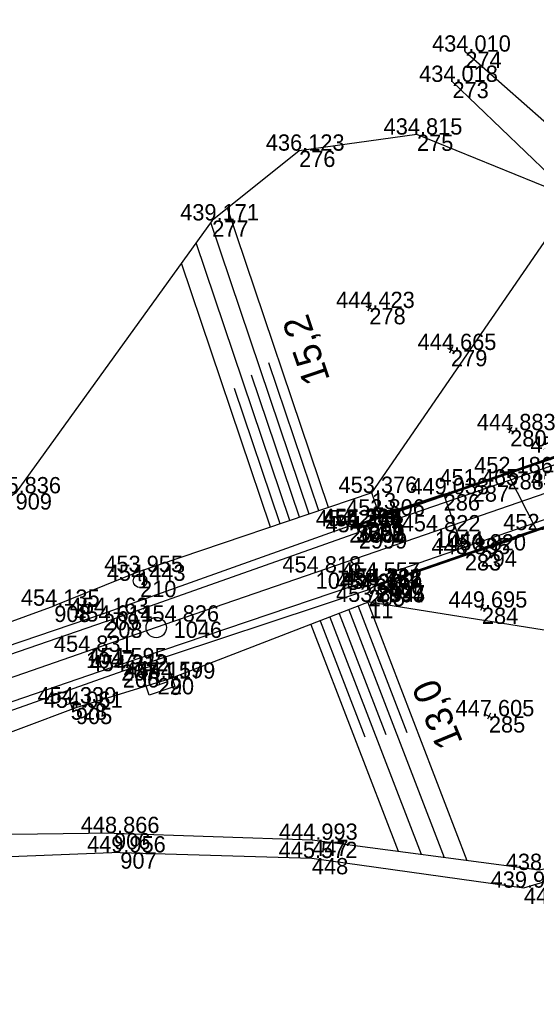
# Model space of a CAD drawing. Extents: x -751615 to -750797, y -1114905 to -1114561.
# Drawn here: x -751212.2 to -751174.1, y -1114734.9 to -1114663.2 of the extents above; entities that cross this region are included whole.
import ezdxf

# ---------------------------------------------------------------- set-up
doc = ezdxf.new("R2010")
doc.units = 0
for name, color, linetype in [('Vrstva 1', 7, 'Continuous'), ('Vrstva 17', 7, 'Continuous'), ('Vrstva 18', 7, 'Continuous'), ('Vrstva 33', 7, 'Continuous'), ('Vrstva 4', 7, 'Continuous'), ('Vrstva 48', 7, 'Continuous'), ('Vrstva 49', 7, 'Continuous'), ('Vrstva 51', 7, 'Continuous'), ('Vrstva 60', 7, 'Continuous'), ('Vrstva 61', 7, 'Continuous'), ('Vrstva 7', 7, 'Continuous')]:
    doc.layers.add(name, color=color, linetype=linetype)

msp = doc.modelspace()

# ---------------------------------------------------------------- linework, layer by layer
at = {"layer": 'Vrstva 1'}
msp.add_lwpolyline([(-751049.798, -1114655.49), (-751059.246, -1114658.755), (-751068.733, -1114662.026), (-751078.259, -1114665.311), (-751087.386, -1114668.46), (-751094.716, -1114670.988), (-751098.18, -1114672.185), (-751107.899, -1114675.542), (-751117.566, -1114678.875), (-751127.151, -1114682.181), (-751136.66, -1114685.456), (-751145.831, -1114688.627), (-751153.169, -1114691.158), (-751162.606, -1114694.412), (-751172.056, -1114697.672), (-751181.572, -1114700.954), (-751190.356, -1114703.987), (-751200.827, -1114707.603), (-751207.289, -1114709.832), (-751216.509, -1114713.014)], dxfattribs=at)
at = {"layer": 'Vrstva 17'}
for points in [[(-751142.673, -1114685.146), (-751163.635, -1114692.354), (-751187.36, -1114700.537)], [(-751141.251, -1114689.537), (-751162.016, -1114696.742), (-751185.869, -1114704.919)]]:
    msp.add_lwpolyline(points, dxfattribs=at)
at = {"layer": 'Vrstva 18'}
for p, q in [((-751176.227, -1114696.67), (-751174.085, -1114700.864)), ((-751180.926, -1114698.222), (-751185.664, -1114699.79)), ((-751179.366, -1114702.637), (-751180.926, -1114698.222)), ((-751185.664, -1114699.79), (-751187.351, -1114700.583)), ((-751179.366, -1114702.637), (-751185.916, -1114704.887))]:
    msp.add_line(p, q, dxfattribs=at)
for points in [[(-751047.485, -1114652.852), (-751074.245, -1114662.097), (-751099.037, -1114670.633), (-751120.593, -1114678.106), (-751141.938, -1114685.464), (-751163.608, -1114692.915), (-751187.181, -1114701.023)], [(-751046.217, -1114656.195), (-751073.081, -1114665.441), (-751097.909, -1114674.024), (-751119.627, -1114681.519), (-751140.891, -1114688.815), (-751162.437, -1114696.278), (-751186.019, -1114704.426)], [(-751142.792, -1114685.118), (-751163.784, -1114692.357), (-751187.386, -1114700.477)], [(-751142.793, -1114685.119), (-751163.784, -1114692.356), (-751187.386, -1114700.477)], [(-751142.776, -1114685.241), (-751163.709, -1114692.446), (-751187.351, -1114700.583)], [(-751141.364, -1114689.506), (-751162.365, -1114696.76), (-751185.916, -1114704.887)], [(-751141.333, -1114689.609), (-751162.305, -1114696.864), (-751185.867, -1114704.985)], [(-751141.334, -1114689.6), (-751162.302, -1114696.872), (-751185.866, -1114704.984)], [(-751187.181, -1114701.023), (-751187.386, -1114700.477), (-751187.386, -1114700.477), (-751187.351, -1114700.583), (-751187.181, -1114701.023)], [(-751186.019, -1114704.426), (-751185.867, -1114704.985), (-751185.866, -1114704.984), (-751185.916, -1114704.887), (-751186.019, -1114704.426)]]:
    msp.add_lwpolyline(points, dxfattribs=at)
for centre, major_axis, ratio, start_param, end_param in [((-751176.059, -1114696.183), (5.5, 1.848), 0.070466, 4.658245, 6.265164), ((-751176.321, -1114696.416), (5.121, 1.873), 0.049725, 3.576163, 4.712471), ((-751175.104, -1114700.819), (4.529, 1.783), 0.086973, 3.454221, 4.905011)]:
    msp.add_ellipse(centre, major_axis=major_axis, ratio=ratio, start_param=start_param, end_param=end_param, dxfattribs=at)
at = {"layer": 'Vrstva 33'}
for p, q in [((-751201.835, -1114712.237), (-751202.161, -1114711.291)), ((-751201.362, -1114712.074), (-751202.308, -1114712.4))]:
    msp.add_line(p, q, dxfattribs=at)
msp.add_lwpolyline([(-751200.727, -1114712.383), (-751202.617, -1114713.035), (-751203.269, -1114711.145), (-751201.379, -1114710.493), (-751200.727, -1114712.383)], dxfattribs=at)
at = {"layer": 'Vrstva 4'}
for p, q in [((-751205.795, -1114707.603), (-751187.181, -1114701.023)), ((-751204.677, -1114710.75), (-751186.019, -1114704.426))]:
    msp.add_line(p, q, dxfattribs=at)
for points in [[(-751047.485, -1114652.852), (-751074.245, -1114662.097), (-751099.037, -1114670.633), (-751120.593, -1114678.106), (-751141.938, -1114685.464), (-751163.608, -1114692.915), (-751187.181, -1114701.023)], [(-751046.217, -1114656.195), (-751073.081, -1114665.441), (-751097.909, -1114674.024), (-751119.627, -1114681.519), (-751140.891, -1114688.815), (-751162.437, -1114696.278), (-751186.019, -1114704.426)], [(-751187.894, -1114700.58), (-751206.028, -1114707.041), (-751231.235, -1114715.596), (-751249.544, -1114721.971), (-751267.723, -1114728.471), (-751285.298, -1114734.541), (-751305.686, -1114741.509), (-751323.628, -1114747.668), (-751344.164, -1114754.785), (-751362.443, -1114761.123), (-751382.646, -1114767.996), (-751419.827, -1114780.907), (-751439.841, -1114787.752), (-751459.648, -1114794.565), (-751479.262, -1114801.395), (-751499.563, -1114808.301), (-751517.656, -1114814.613), (-751524.467, -1114817.135), (-751524.911, -1114817.646)], [(-751187.894, -1114700.58), (-751187.351, -1114700.583), (-751187.181, -1114701.023)], [(-751186.455, -1114705.269), (-751185.916, -1114704.887), (-751186.019, -1114704.426)], [(-751186.455, -1114705.269), (-751204.57, -1114711.262), (-751229.26, -1114719.967), (-751248.511, -1114726.389), (-751266.031, -1114732.591), (-751283.828, -1114738.73), (-751304.211, -1114745.766), (-751322.374, -1114751.898), (-751342.612, -1114758.897), (-751360.965, -1114765.168), (-751381.114, -1114772.121), (-751418.537, -1114784.997), (-751438.613, -1114791.912), (-751458.172, -1114798.656), (-751477.814, -1114805.419), (-751497.901, -1114812.476), (-751516.513, -1114818.688), (-751522.385, -1114820.606), (-751523.195, -1114820.521)], [(-751205.795, -1114707.603), (-751230.97, -1114716.264), (-751249.417, -1114722.675), (-751267.451, -1114728.869), (-751285.106, -1114734.872), (-751305.56, -1114741.936), (-751323.346, -1114748.135), (-751343.956, -1114755.234), (-751362.406, -1114761.583), (-751382.455, -1114768.543), (-751419.68, -1114781.407), (-751439.787, -1114788.305), (-751459.372, -1114795.057), (-751479.147, -1114801.881), (-751499.337, -1114808.873), (-751517.572, -1114815.159), (-751524.911, -1114817.646)], [(-751204.677, -1114710.75), (-751229.564, -1114719.281), (-751248.527, -1114725.936), (-751266.247, -1114732.037), (-751284.071, -1114738.15), (-751304.213, -1114745.084), (-751322.473, -1114751.338), (-751342.638, -1114758.269), (-751361.135, -1114764.639), (-751381.339, -1114771.707), (-751418.714, -1114784.623), (-751438.728, -1114791.466), (-751458.255, -1114798.22), (-751477.955, -1114804.997), (-751498.184, -1114811.907), (-751516.629, -1114818.238), (-751523.195, -1114820.521)]]:
    msp.add_lwpolyline(points, dxfattribs=at)
at = {"layer": 'Vrstva 48'}
for p, q in [((-751189.418, -1114699.201), (-751196.867, -1114677.15)), ((-751190.839, -1114699.681), (-751198.095, -1114678.2)), ((-751192.26, -1114700.161), (-751199.173, -1114679.696)), ((-751193.682, -1114700.641), (-751200.251, -1114681.192)), ((-751190.129, -1114699.441), (-751193.809, -1114688.545)), ((-751191.55, -1114699.921), (-751195.092, -1114689.435)), ((-751192.971, -1114700.401), (-751196.342, -1114690.423)), ((-751187.924, -1114706.736), (-751180.903, -1114724.972)), ((-751187.224, -1114706.466), (-751183.64, -1114715.775)), ((-751186.524, -1114706.197), (-751179.209, -1114725.197)), ((-751190.023, -1114707.544), (-751186.734, -1114716.089)), ((-751189.324, -1114707.275), (-751182.597, -1114724.747)), ((-751188.624, -1114707.005), (-751185.187, -1114715.932)), ((-751190.723, -1114707.814), (-751184.291, -1114724.521))]:
    msp.add_line(p, q, dxfattribs=at)
at = {"layer": 'Vrstva 49'}
for p, q in [((-751186.22, -1114698.121), (-751171.305, -1114676.437)), ((-751186.182, -1114684.61), (-751186.632, -1114684.39)), ((-751186.297, -1114684.275), (-751186.517, -1114684.725)), ((-751180.163, -1114687.702), (-751180.613, -1114687.482)), ((-751180.278, -1114687.367), (-751180.498, -1114687.817)), ((-751175.803, -1114693.61), (-751176.253, -1114693.39)), ((-751175.918, -1114693.275), (-751176.138, -1114693.725)), ((-751203.477, -1114703.95), (-751209.62, -1114706.435)), ((-751186.41, -1114706.153), (-751159.892, -1114710.39)), ((-751231.525, -1114714.481), (-751209.62, -1114706.435)), ((-751177.885, -1114706.682), (-751178.335, -1114706.462)), ((-751178, -1114706.347), (-751178.22, -1114706.797)), ((-751177.37, -1114714.687), (-751177.82, -1114714.467)), ((-751177.485, -1114714.352), (-751177.705, -1114714.802))]:
    msp.add_line(p, q, dxfattribs=at)
for points in [[(-751159.892, -1114710.39), (-751159.564, -1114697.887), (-751162.611, -1114687.691), (-751171.305, -1114676.437), (-751182.896, -1114671.724), (-751191.58, -1114672.907), (-751197.985, -1114678.047), (-751212.472, -1114698.152), (-751234.949, -1114713.279), (-751244.9, -1114718.575)], [(-751185.664, -1114699.79), (-751186.22, -1114698.121), (-751203.477, -1114703.95)], [(-751185.916, -1114704.887), (-751179.366, -1114702.637), (-751180.926, -1114698.222), (-751185.664, -1114699.79)], [(-751185.916, -1114704.887), (-751186.41, -1114706.153), (-751201.101, -1114711.809)], [(-751201.101, -1114711.809), (-751208.027, -1114713.956), (-751228.322, -1114721.57), (-751240.07, -1114724.297)], [(-751205.217, -1114723.182), (-751227.836, -1114723.486), (-751240.236, -1114725.654)], [(-751205.217, -1114723.182), (-751190.613, -1114723.681), (-751173.898, -1114725.903), (-751163.172, -1114723.646)], [(-751204.754, -1114724.609), (-751190.638, -1114725.023), (-751175.014, -1114727.21), (-751163.172, -1114723.646)], [(-751204.754, -1114724.609), (-751227.195, -1114725.505), (-751238.195, -1114726.494), (-751253.205, -1114735.378), (-751297.853, -1114756.709), (-751332.903, -1114772.385), (-751375.498, -1114786.511), (-751400.696, -1114793.558), (-751443.206, -1114803.356), (-751482.539, -1114812.284)]]:
    msp.add_lwpolyline(points, dxfattribs=at)
at = {"layer": 'Vrstva 51'}
for points in [[(-751179.332, -1114665.61), (-751169.189, -1114674.547), (-751160.093, -1114686.607), (-751155.976, -1114695.63), (-751150.02, -1114707.804), (-751142.251, -1114727.926)], [(-751180.281, -1114667.838), (-751171.305, -1114676.437), (-751162.611, -1114687.691), (-751158.117, -1114696.777), (-751151.768, -1114708.954), (-751144.608, -1114729.118)]]:
    msp.add_lwpolyline(points, dxfattribs=at)
at = {"layer": 'Vrstva 60'}
for p, q in [((-751179.332, -1114665.61), (-751179.332, -1114665.61)), ((-751180.281, -1114667.838), (-751180.281, -1114667.838)), ((-751182.896, -1114671.724), (-751182.896, -1114671.724)), ((-751191.58, -1114672.907), (-751191.58, -1114672.907)), ((-751197.985, -1114678.047), (-751197.985, -1114678.047)), ((-751186.407, -1114684.5), (-751186.407, -1114684.5)), ((-751180.388, -1114687.592), (-751180.388, -1114687.592)), ((-751176.028, -1114693.5), (-751176.028, -1114693.5)), ((-751176.227, -1114696.67), (-751176.227, -1114696.67)), ((-751186.22, -1114698.121), (-751186.22, -1114698.121)), ((-751180.926, -1114698.222), (-751180.926, -1114698.222)), ((-751178.786, -1114697.568), (-751178.786, -1114697.568)), ((-751185.664, -1114699.79), (-751185.664, -1114699.79)), ((-751187.894, -1114700.58), (-751187.894, -1114700.58)), ((-751187.386, -1114700.477), (-751187.386, -1114700.477)), ((-751187.386, -1114700.477), (-751187.386, -1114700.477)), ((-751187.36, -1114700.537), (-751187.36, -1114700.537)), ((-751187.351, -1114700.583), (-751187.351, -1114700.583)), ((-751187.181, -1114701.023), (-751187.181, -1114701.023)), ((-751181.572, -1114700.954), (-751181.572, -1114700.954)), ((-751174.085, -1114700.864), (-751174.085, -1114700.864)), ((-751178.209, -1114702.362), (-751178.209, -1114702.362)), ((-751179.366, -1114702.637), (-751179.366, -1114702.637)), ((-751203.477, -1114703.95), (-751203.477, -1114703.95)), ((-751190.356, -1114703.987), (-751190.356, -1114703.987)), ((-751203.297, -1114704.599), (-751203.297, -1114704.599)), ((-751186.019, -1114704.426), (-751186.019, -1114704.426)), ((-751186.455, -1114705.269), (-751186.455, -1114705.269)), ((-751185.916, -1114704.887), (-751185.916, -1114704.887)), ((-751185.869, -1114704.919), (-751185.869, -1114704.919)), ((-751185.867, -1114704.985), (-751185.867, -1114704.985)), ((-751185.866, -1114704.984), (-751185.866, -1114704.984)), ((-751186.41, -1114706.153), (-751186.41, -1114706.153)), ((-751209.62, -1114706.435), (-751209.62, -1114706.435)), ((-751178.11, -1114706.572), (-751178.11, -1114706.572)), ((-751206.028, -1114707.041), (-751206.028, -1114707.041)), ((-751205.795, -1114707.603), (-751205.795, -1114707.603)), ((-751200.827, -1114707.603), (-751200.827, -1114707.603)), ((-751207.289, -1114709.832), (-751207.289, -1114709.832)), ((-751204.677, -1114710.75), (-751204.677, -1114710.75)), ((-751204.57, -1114711.262), (-751204.57, -1114711.262)), ((-751201.998, -1114711.764), (-751201.998, -1114711.764)), ((-751201.101, -1114711.809), (-751201.101, -1114711.809)), ((-751208.405, -1114713.632), (-751208.405, -1114713.632)), ((-751208.027, -1114713.956), (-751208.027, -1114713.956)), ((-751177.595, -1114714.577), (-751177.595, -1114714.577)), ((-751205.217, -1114723.182), (-751205.217, -1114723.182)), ((-751190.613, -1114723.681), (-751190.613, -1114723.681)), ((-751204.754, -1114724.609), (-751204.754, -1114724.609)), ((-751190.638, -1114725.023), (-751190.638, -1114725.023)), ((-751175.014, -1114727.21), (-751175.014, -1114727.21))]:
    msp.add_line(p, q, dxfattribs=at)
at = {"layer": 'Vrstva 7'}
for p, q in [((-751203.25, -1114704.583), (-751203.344, -1114704.615)), ((-751208.242, -1114714.105), (-751208.568, -1114713.159)), ((-751207.932, -1114713.469), (-751208.878, -1114713.795))]:
    msp.add_line(p, q, dxfattribs=at)
for centre, radius in [((-751203.297, -1114704.599), 0.5), ((-751202.108, -1114708.045), 0.75)]:
    msp.add_circle(centre, radius, dxfattribs=at)

# ---------------------------------------------------------------- texts
at = {"layer": 'Vrstva 48'}
for s, rotation, p in [('15,2', 108.66373, (-751189.287, -1114689.762)), ('13,0', 112.42781, (-751179.487, -1114716.485))]:
    msp.add_text(s, height=2, rotation=rotation, dxfattribs=at).set_placement(p)
at = {"layer": 'Vrstva 60'}
for s, p in [('274', (-751179.332, -1114666.81)), ('273', (-751180.281, -1114669.038)), ('275', (-751182.896, -1114672.924)), ('276', (-751191.58, -1114674.107)), ('277', (-751197.985, -1114679.247)), ('278', (-751186.407, -1114685.7)), ('279', (-751180.388, -1114688.792)), ('280', (-751176.028, -1114694.7)), ('288', (-751176.227, -1114697.87)), ('287', (-751178.786, -1114698.768)), ('909', (-751212.472, -1114699.352)), ('13', (-751186.22, -1114699.321)), ('286', (-751180.926, -1114699.422)), ('14', (-751185.664, -1114700.99)), ('204', (-751187.894, -1114701.78)), ('3000', (-751187.386, -1114701.677)), ('3001', (-751187.386, -1114701.677)), ('3002', (-751187.351, -1114701.783)), ('2998', (-751187.36, -1114701.737)), ('2999', (-751187.181, -1114702.223)), ('1044', (-751181.572, -1114702.154)), ('294', (-751178.209, -1114703.562)), ('283', (-751179.366, -1114703.837)), ('1', (-751203.477, -1114705.15)), ('1045', (-751190.356, -1114705.187)), ('210', (-751203.297, -1114705.799)), ('2996', (-751186.019, -1114705.626)), ('205', (-751186.455, -1114706.469)), ('2993', (-751185.916, -1114706.087)), ('2997', (-751185.869, -1114706.119)), ('2995', (-751185.867, -1114706.185)), ('2994', (-751185.866, -1114706.184)), ('11', (-751186.41, -1114707.353)), ('908', (-751209.62, -1114707.635)), ('284', (-751178.11, -1114707.772)), ('209', (-751206.028, -1114708.241)), ('208', (-751205.795, -1114708.803)), ('1046', (-751200.827, -1114708.803)), ('1047', (-751207.289, -1114711.032)), ('207', (-751204.677, -1114711.95)), ('206', (-751204.57, -1114712.462)), ('220', (-751201.998, -1114712.964)), ('9', (-751201.101, -1114713.009)), ('528', (-751208.405, -1114714.832)), ('905', (-751208.027, -1114715.156)), ('285', (-751177.595, -1114715.777)), ('906', (-751205.217, -1114724.382)), ('447', (-751190.613, -1114724.881)), ('907', (-751204.754, -1114725.809)), ('448', (-751190.638, -1114726.223)), ('449', (-751175.014, -1114728.41))]:
    msp.add_text(s, height=1.2, dxfattribs=at).set_placement(p)
at = {"layer": 'Vrstva 61'}
for s, p in [('434.010', (-751181.783, -1114665.61)), ('434.018', (-751182.735, -1114667.838)), ('434.815', (-751185.352, -1114671.724)), ('436.123', (-751194.032, -1114672.907)), ('439.171', (-751200.342, -1114678.047)), ('444.423', (-751188.859, -1114684.5)), ('444.665', (-751182.844, -1114687.592)), ('444.883', (-751178.48, -1114693.5)), ('450.499', (-751174.532, -1114695.15)), ('452.186', (-751178.679, -1114696.67)), ('451.465', (-751181.242, -1114697.568)), ('454.822', (-751174.504, -1114697.672)), ('445.836', (-751214.924, -1114698.152)), ('453.376', (-751188.672, -1114698.121)), ('449.033', (-751183.378, -1114698.222)), ('453.806', (-751188.116, -1114699.79)), ('454.235', (-751190.35, -1114700.58)), ('454.505', (-751189.842, -1114700.477)), ('454.206', (-751189.838, -1114700.477)), ('455.743', (-751189.812, -1114700.537)), ('454.234', (-751189.802, -1114700.583)), ('452.163', (-751176.537, -1114700.864)), ('454.568', (-751189.635, -1114701.023)), ('454.822', (-751184.02, -1114700.954)), ('450.820', (-751180.66, -1114702.362)), ('448.895', (-751181.822, -1114702.637)), ('453.955', (-751205.933, -1114703.95)), ('454.818', (-751192.81, -1114703.987)), ('454.557', (-751188.471, -1114704.426)), ('454.443', (-751205.749, -1114704.599)), ('454.486', (-751188.319, -1114704.985)), ('454.187', (-751188.318, -1114704.984)), ('455.722', (-751188.317, -1114704.919)), ('454.211', (-751188.273, -1114704.887)), ('454.238', (-751188.909, -1114705.269)), ('454.135', (-751212.076, -1114706.435)), ('453.894', (-751188.861, -1114706.153)), ('449.695', (-751180.566, -1114706.572)), ('454.163', (-751208.48, -1114707.041)), ('454.611', (-751208.152, -1114707.603)), ('454.826', (-751203.279, -1114707.603)), ('454.831', (-751209.646, -1114709.832)), ('454.595', (-751207.133, -1114710.75)), ('454.312', (-751207.018, -1114711.262)), ('454.159', (-751204.452, -1114711.764)), ('454.179', (-751203.555, -1114711.809)), ('454.330', (-751210.856, -1114713.632)), ('454.061', (-751210.384, -1114713.956)), ('447.605', (-751180.051, -1114714.577)), ('448.866', (-751207.669, -1114723.182)), ('444.993', (-751193.065, -1114723.681)), ('449.956', (-751207.206, -1114724.609)), ('445.572', (-751193.086, -1114725.023)), ('438.968', (-751176.352, -1114725.903)), ('439.953', (-751177.466, -1114727.21))]:
    msp.add_text(s, height=1.2, dxfattribs=at).set_placement(p)

doc.saveas('drawing.dxf')
